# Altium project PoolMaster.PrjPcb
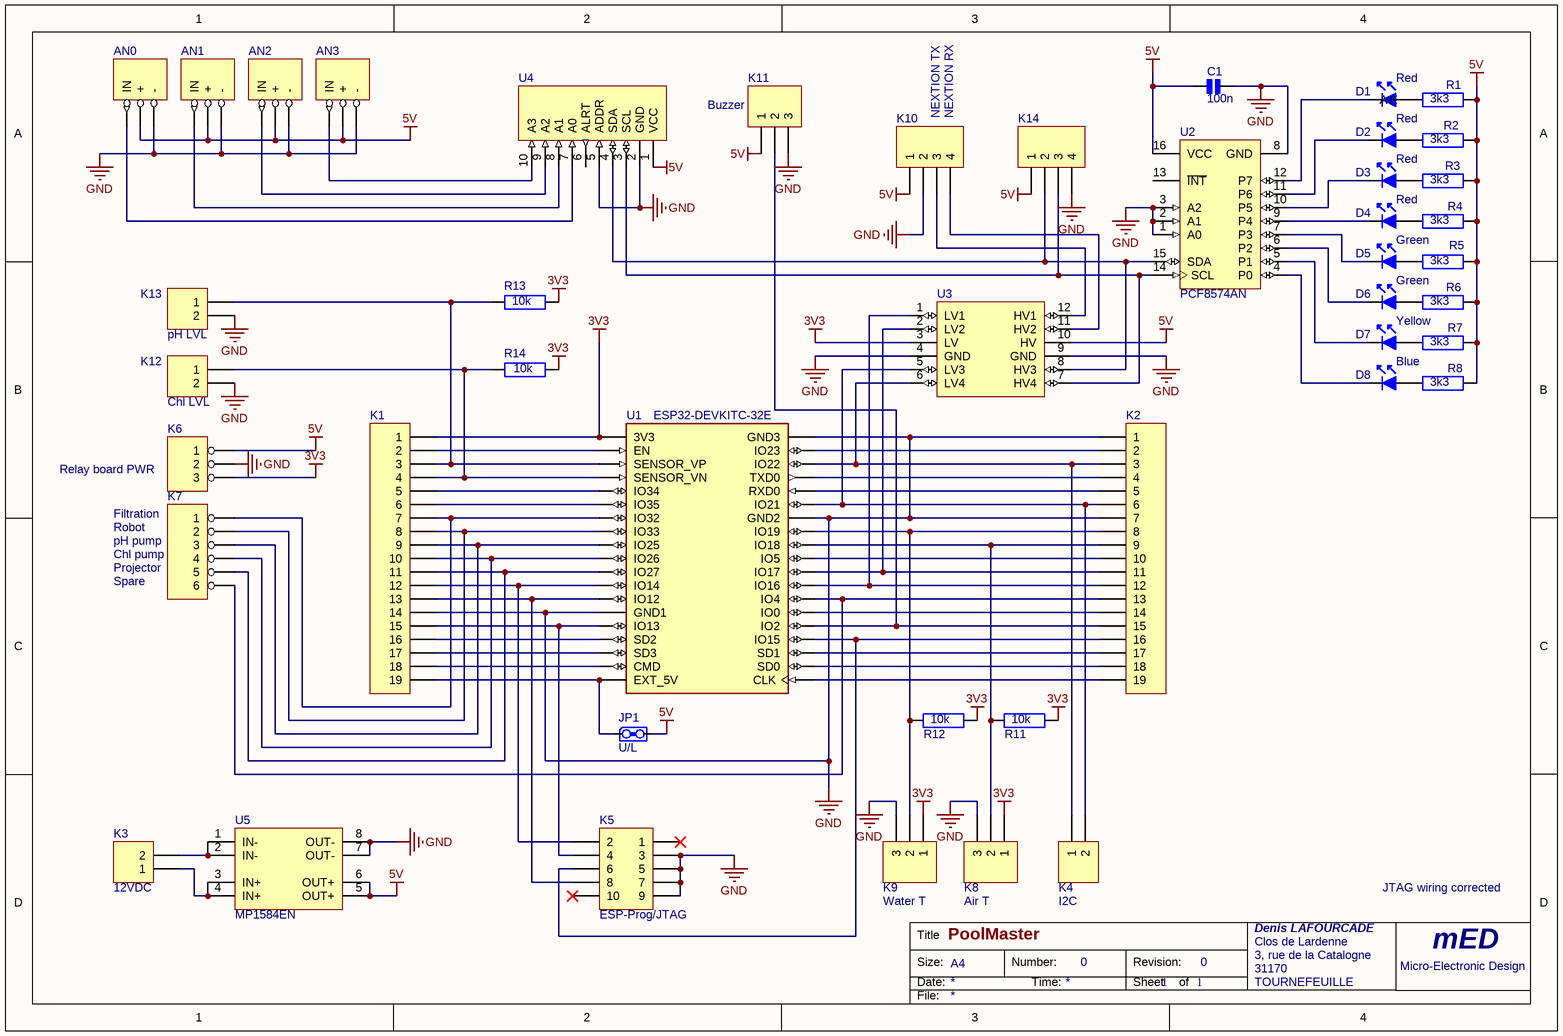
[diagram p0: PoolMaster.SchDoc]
1 sheet, 45 parts. Net scope: global (net labels, ports and power ports of the same name join across sheets).
Board file: PoolMaster.PcbDoc

## Sheet PoolMaster.SchDoc: PoolMaster
size A4; Organization: Denis LAFOURCADE; Address1: Clos de Lardenne; Address2: 3, rue de la Catalogne; Address3: 31170; Address4: TOURNEFEUILLE; DocumentNumber: 0; Revision: 0; SheetNumber: 1; SheetTotal: 1

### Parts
AN0  HEADER 3  [JST-1X3]  (value not drawn)
AN1  HEADER 3  [JST-1X3]  (value not drawn)
AN2  HEADER 3  [JST-1X3]  (value not drawn)
AN3  HEADER 3  [JST-1X3]  (value not drawn)
C1  100n  [0805C-GENERIC]
D1  Red  [TOPLED-RED]
D2  Red  [TOPLED-RED]
D3  Red  [TOPLED-RED]
D4  Red  [TOPLED-RED]
D5  Green  [TOPLED-GREEN]
D6  Green  [TOPLED-GREEN]
D7  Yellow  [TOPLED-YELLOW]
D8  Blue  [TOPLED-BLUE]
JP1  U/L  [2_PADS]
K1  Header 19  [HDR1X19]  (value not drawn)
K2  Header 19  [HDR1X19]  (value not drawn)
K3  12VDC  [MKDS15_2RMI]
K4  I2C  [HEADER-1X2]
K5  ESP-Prog/JTAG  [HE10_10]
K6  HEADER 3  [HEADER-1X3]  (value not drawn)
K7  HEADER 6  [HEADER-1X6]  (value not drawn)
K8  Air T  [JST-1X3]
K9  Water T  [JST-1X3]
K10  Display  [HEADER-1X4]  (value not drawn)
K11  Buzzer  [HEADER-1X3]
K12  Chl LVL  [HEADER-1X2]
K13  pH LVL  [HEADER-1X2]
K14  I2C-5V  [HEADER-1X4]  (value not drawn)
R1  3k3  [0805R-3K3]
R2  3k3  [0805R-3K3]
R3  3k3  [0805R-3K3]
R4  3k3  [0805R-3K3]
R5  3k3  [0805R-3K3]
R6  3k3  [0805R-3K3]
R7  3k3  [0805R-3K3]
R8  3k3  [0805R-3K3]
R11  10k  [0805R-10K]
R12  10k  [0805R-10K]
R13  10k  [0805R-10K]
R14  10k  [0805R-10K]
U1  ESP32-DEVKITC-32E  [MODULE_ESP32-DEVKITC-32D]
U2  PCF8574AN  [DIP16]
U3  SHIFTER 4CH  [SHIFTER 4CH]  (value not drawn)
U4  ADS1115  [ADS1115 Module]  (value not drawn)
U5  MP1584EN  [MP1884EN]

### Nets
3V3: K1.1 K6.3 K8.1 K9.1 R11.1 R12.1 R13.1 R14.1 U1.1(3V3) U3.3(LV)
5V: AN0.2(+) AN1.2(+) AN2.2(+) AN3.2(+) C1.1 JP1.2 K6.1 K10.1 K11.1 K14.1 R1.1 R2.1 R3.1 R4.1 R5.1 R6.1 R7.1 R8.1 U2.16(VCC) U3.10(HV) U4.1(VCC) U5.5(OUT+) U5.6(OUT+)
GND: AN0.3(-) AN1.3(-) AN2.3(-) AN3.3(-) C1.2 K1.14 K2.1 K2.7 K5.3 K5.5 K5.7 K5.9 K6.2 K8.3 K9.3 K10.2 K11.3 K12.2 K13.2 K14.4 U1.14(GND1) U1.20(GND3) U1.26(GND2) U2.1(A0) U2.2(A1) U2.3(A2) U2.8(GND) U3.4(GND) U3.9(GND) U4.2(GND) U4.5(ADDR) U5.7(OUT-) U5.8(OUT-)
NetAN0_1: AN0.1(IN) U4.7(A0)
NetAN1_1: AN1.1(IN) U4.8(A1)
NetAN2_1: AN2.1(IN) U4.9(A2)
NetAN3_1: AN3.1(IN) U4.10(A3)
NetD1_1: D1.1(A) R1.2
NetD1_2: D1.2(K) U2.12(P7)
NetD2_1: D2.1(A) R2.2
NetD2_2: D2.2(K) U2.11(P6)
NetD3_1: D3.1(A) R3.2
NetD3_2: D3.2(K) U2.10(P5)
NetD4_1: D4.1(A) R4.2
NetD4_2: D4.2(K) U2.9(P4)
NetD5_1: D5.1(A) R5.2
NetD5_2: D5.2(K) U2.7(P3)
NetD6_1: D6.1(A) R6.2
NetD6_2: D6.2(K) U2.6(P2)
NetD7_1: D7.1(A) R7.2
NetD7_2: D7.2(K) U2.5(P1)
NetD8_1: D8.1(A) R8.2
NetD8_2: D8.2(K) U2.4(P0)
NetJP1_1: JP1.1 K1.19 U1.19(EXT_5V)
NetK1_2: K1.2 U1.2(EN)
NetK1_3: K1.3 K13.1 R13.2 U1.3(SENSOR_VP)
NetK1_4: K1.4 K12.1 R14.2 U1.4(SENSOR_VN)
NetK1_5: K1.5 U1.5(IO34)
NetK1_6: K1.6 U1.6(IO35)
NetK1_7: K1.7 K7.1 U1.7(IO32)
NetK1_8: K1.8 K7.2 U1.8(IO33)
NetK1_9: K1.9 K7.3 U1.9(IO25)
NetK1_10: K1.10 K7.4 U1.10(IO26)
NetK1_11: K1.11 K7.5 U1.11(IO27)
NetK1_12: K1.12 K5.2 U1.12(IO14)
NetK1_13: K1.13 K5.8 U1.13(IO12)
NetK1_15: K1.15 K5.4 U1.15(IO13)
NetK1_16: K1.16 U1.16(SD2)
NetK1_17: K1.17 U1.17(SD3)
NetK1_18: K1.18 U1.18(CMD)
NetK2_2: K2.2 U1.21(IO23)
NetK2_3: K2.3 K4.1 U1.22(IO22) U3.6(LV4)
NetK2_4: K2.4 U1.23(TXD0)
NetK2_5: K2.5 U1.24(RXD0)
NetK2_6: K2.6 K4.2 U1.25(IO21) U3.5(LV3)
NetK2_8: K2.8 K9.2 R12.2 U1.27(IO19)
NetK2_9: K2.9 K8.2 R11.2 U1.28(IO18)
NetK2_10: K2.10 U1.29(IO5)
NetK2_11: K2.11 U1.30(IO17) U3.2(LV2)
NetK2_12: K2.12 U1.31(IO16) U3.1(LV1)
NetK2_13: K2.13 K7.6 U1.32(IO4)
NetK2_14: K2.14 U1.33(IO0)
NetK2_15: K2.15 K11.2 U1.34(IO2)
NetK2_16: K2.16 K5.6 U1.35(IO15)
NetK2_17: K2.17 U1.36(SD1)
NetK2_18: K2.18 U1.37(SD0)
NetK2_19: K2.19 U1.38(CLK)
NetK3_1: K3.1 U5.3(IN+) U5.4(IN+)
NetK3_2: K3.2 U5.1(IN-) U5.2(IN-)
NetK10_3: K10.3 U3.12(HV1)
NetK10_4: K10.4 U3.11(HV2)
NetK14_2: K14.2 U2.15(SDA) U3.8(HV3) U4.4(SDA)
NetK14_3: K14.3 U2.14(SCL) U3.7(HV4) U4.3(SCL)

Not connected (* = marked no-connect by the designer): K5 1* 10*; U2 13(~{INT}); U4 6(ALRT)

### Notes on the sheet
- (near K10) NEXTION TX
- (near K10) NEXTION RX
- Relay board PWR
- Filtration
- Robot
- pH pump
- (near K7) Chl pump
- (near K7) Projector
- Spare
- JTAG wiring corrected

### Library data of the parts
C1 = CAP: Capacitor
D1-D8 = LED: pin to pad: 1>A 2>K
JP1 = JUMPER
K1 K2 = Header 19: Header, 19-Pin
K3 K4 K12 K13 = Header 2: Header, 2-Pin
K5 = Header 5X2: Header, 5-Pin, Dual row
K8 K9 K11 = Header 3: Header, 3-Pin
K10 K14 = Header 4: Header, 4-Pin
R1-R8 R11-R14 = RES2: Resistor
U1 = ESP32-DEVKITC-32D: - Transceiver; 802.11 b/g/n _Wi-Fi, WiFi, WLAN_, BluetoothÂ® Smart Ready 4.x Dual Mode For Use With ESP-WROOM-32; MF: Espressif Systems
U2 = PCF8574AN: Remote 8-Bit I/O Expander for I2C-Bus, 2.5 to 6 V, -40 to 85 degC, 16-pin PDIP (N), Pb-Free (RoHS); Manufacturer: Texas Instruments; Eco-Plan: Green (RoHS & no Sb/Br); SubFamily: I2C IO Expander; Voltage Nodes(V): 5, 3.3; Interrupt Output: Yes; Reset Input: No; fSCLK(Max)(MHz): 0.1; VCC(Min)(V): 2.5; VCC(Max)(V): 6; Max Frequency(kHz): 100; I2C Address: 0111 xxx; # of I/Os: 8; Vcc range(V): 2.5 to 6.0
